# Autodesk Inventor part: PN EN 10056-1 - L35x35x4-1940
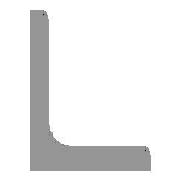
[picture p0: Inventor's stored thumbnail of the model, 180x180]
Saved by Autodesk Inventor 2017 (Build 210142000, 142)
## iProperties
IsCustomPart: 1
Created: 2020-07
Part Number: PN EN 10056-1 - L35x35x4-1940
Material: Stal, miękka
Description: Kątownik równoramienny
Document SubType Name: Modeling
Standard: PN
Designer: X
Standards Organization: PN
Language: pl-PL
Size Designation: L35x35x4
Categories: <MemberInstance><Categories><Category DisplayName="Kształtowniki konstrukcyjne" InternalName="089c4875-fa83-4c05-b084-43b9cc11f5ed" Mnemonic="GRDR"><CategoryPar
Stock Number: L35x35x4
Density: 7.85 g/cm^3
Appearance: Częściowo polerowana
_CCFamilyMember: 60
_CCFamilyDisplayName: PN EN 10056-1 (Kątownik równoramienny) - Kątownik równoramienny
_FrameMemberDoc: Frame Member File
_Version: 15.0.0
_GetPNFromCC: 1
G_L: 1940,000 mm
G_W: 35,000 mm
G_H: 35,000 mm
Author: X
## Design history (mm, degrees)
node "Płaszczyzna początkowa"
node "Płaszczyzna końcowa"
sketch "Szkic"
  geometry: L1 (-6.019, -1.019)-(-6.019, 22.481); L2 (-10.019, 24.981)-(-8.519, 24.981); L3 (-10.019, -10.019)-(-10.019, 24.981); L4 (-10.019, -10.019)-(24.981, -10.019); L5 (24.981, -8.519)-(24.981, -10.019); L6 (-1.019, -6.019)-(22.481, -6.019); L7 (0, 32.602)-(0, -17.123) reference; L8 (-17.123, 0)-(32.602, 0) reference; A1 r 5 centre (-1.019, -1.019) between (-6.019, -1.019) and (-1.019, -6.019); A2 r 2.5 centre (-8.519, 22.481) between (-6.019, 22.481) and (-8.519, 24.981); A3 r 2.5 centre (22.481, -8.519) between (24.981, -8.519) and (22.481, -6.019); 3 further points
  constraints: 12 end point, 6 point on circle, 6 point on line, 6 tangent, 3 centre point, 3 horizontal, 3 vertical, 1 equal radius
  dimensions: "d4" = 35 distance of L3.start L4.end (= b); "d6" = 35 distance of L3.start L2.start (= b); "d8" = 4 distance of point (24.981, -6.019) L4.end (= ParT); "d10" = 4 distance of L2.start point (-6.019, 24.981) (= ParT); "d17" = 5 radius of A1 (= R); "d18" = 2.5 radius of A2 (= R1); "d19" = 10.01931 distance between parallel lines of L8 L4 (= ex); "d20" = 10.01931 distance between parallel lines of L3 L7 (= d19)
extrude "Bryła" new body sketch "Szkic" stored distance "d11" = 1940 (= G_L); taper "d12" = 0 deg
node "Driven Length"
  sketch "Sketch3"
    geometry: L1 (0, 0)-(10, 0) reference
    constraints: 2 end point, 1 horizontal
  workplane "Work Plane10"
  sketch "Sketch4"
    geometry: L1 (-2, 0)-(12, 0) reference; L2 (-2, 1940)-(12, 1940) reference
    dimensions: "d24" = 1940 distance between parallel lines of L1 L2 (derived)
body "Solid1"
other parameters: "b" = 35 [user parameter; used in 3 equation terms], "ParT" = 4 [user parameter; used in 3 equation terms], "R" = 5 [user parameter; used in 1 equation term], "R1" = 2.5 [user parameter; used in 1 equation term], "G_L" = 1940 (= d24) [user parameter; used in 1 equation term], "d7" = 4 (derived), "d9" = 4 (derived), "ex" = 10.01931 (computed from b, ParT) [user parameter; used in 1 equation term], "G_OFFSET_START" = 0 [user parameter; used in 1 equation term], "G_OFFSET_END" = 0 [user parameter; used in 1 equation term], "d21" = 0 (computed from G_OFFSET_START), "d23" = 90 deg
